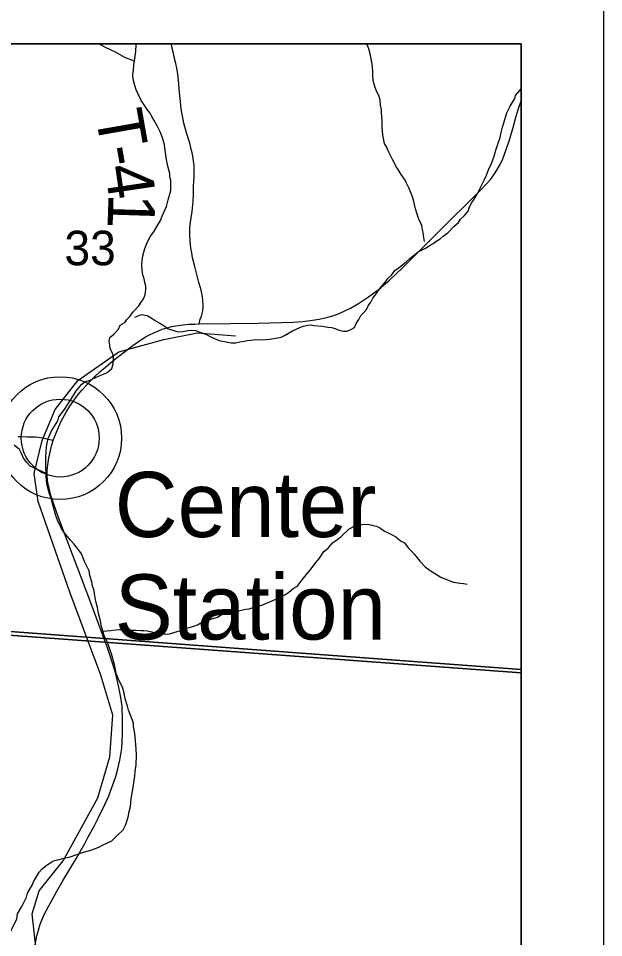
# Model space of a CAD drawing. Extents: x 0 to 82.7, y -0.2 to 22.
# Drawn here: x 8.291 to 9, y 19.817 to 20.931 of the extents above; entities that cross this region are included whole.
import ezdxf

# ---------------------------------------------------------------- set-up
doc = ezdxf.new("R2010")
doc.units = 0
for name, color, linetype in [('GM_X_County_Road', 7, 'Continuous'), ('GM_X_Minor_River', 7, 'Continuous'), ('GM_X_Rail_Line', 7, 'Continuous'), ('GM_X_Section_Text', 7, 'Continuous'), ('GM_X_State_Route', 7, 'Continuous'), ('GM_X_Township_Road', 7, 'Continuous'), ('GM_X_Township_Road_Text', 7, 'Continuous'), ('GM_X_Township_Text', 7, 'Continuous'), ('GM_X_Unincorporated', 7, 'Continuous'), ('GM_X_Unincorporated_Location', 7, 'Continuous'), ('GM_X_Unincorporated_Text', 7, 'Continuous'), ('SH_Cut_Line', 7, 'Continuous'), ('SH_Data', 7, 'Continuous')]:
    doc.layers.add(name, color=color, linetype=linetype)

msp = doc.modelspace()

# ---------------------------------------------------------------- linework, layer by layer
at = {"layer": 'GM_X_County_Road'}
for points in [[(8.9, 20.1421), (8.9, 20.9), (8.0024, 20.9), (7.9492, 20.2127)], [(8.9, 19.3224), (8.9, 20.1421), (7.9492, 20.2127), (7.8698, 19.2002), (8.8838, 19.1258)]]:
    msp.add_lwpolyline(points, close=True, dxfattribs=at)
msp.add_lwpolyline([(8.2907, 20.4244), (8.2947, 20.4244), (8.3015, 20.4241), (8.3116, 20.4239), (8.3204, 20.4229), (8.3271, 20.4212), (8.333, 20.4197)], dxfattribs=at)
at = {"layer": 'GM_X_Minor_River'}
for points in [[(8.4314, 20.8791), (8.4207, 20.883), (8.4086, 20.89), (8.3966, 20.8957), (8.3885, 20.9)], [(8.402, 20.5306), (8.4017, 20.5348), (8.401, 20.5398), (8.4018, 20.5443), (8.4064, 20.5484), (8.4122, 20.5545), (8.4141, 20.5594), (8.4198, 20.5623), (8.4225, 20.5661), (8.426, 20.5699), (8.4302, 20.5759), (8.4368, 20.5826), (8.4398, 20.5872), (8.4425, 20.5913), (8.4445, 20.5959), (8.4453, 20.6027), (8.4454, 20.6065), (8.4443, 20.6111), (8.4432, 20.6153), (8.4417, 20.6202), (8.441, 20.6259), (8.4404, 20.632), (8.4408, 20.6377), (8.4416, 20.6434), (8.444, 20.6521), (8.4475, 20.66), (8.451, 20.6672), (8.4549, 20.6725), (8.4595, 20.68), (8.463, 20.6861), (8.4653, 20.6914), (8.4681, 20.6978), (8.4704, 20.7031), (8.4724, 20.711), (8.474, 20.7167), (8.4755, 20.7224), (8.4757, 20.7349), (8.4746, 20.7391), (8.4743, 20.7429), (8.4721, 20.7517), (8.4699, 20.762), (8.4696, 20.7658), (8.4689, 20.7708), (8.4678, 20.7776), (8.466, 20.7849), (8.4631, 20.7925), (8.459, 20.8009), (8.4553, 20.8074), (8.4527, 20.812), (8.4505, 20.8162), (8.4471, 20.8204), (8.4441, 20.825), (8.4396, 20.8316), (8.4359, 20.8392), (8.4337, 20.8442), (8.4319, 20.8495), (8.4301, 20.8572), (8.4294, 20.8625), (8.4302, 20.8682), (8.4306, 20.8746), (8.4319, 20.8822), (8.4331, 20.8909), (8.4336, 20.8993), (8.4336, 20.9)], [(8.7829, 20.6607), (8.7818, 20.668), (8.7815, 20.6721), (8.78, 20.6767), (8.7797, 20.6805), (8.7767, 20.6866), (8.7742, 20.6939), (8.772, 20.7), (8.7709, 20.7053), (8.7702, 20.7092), (8.7683, 20.7149), (8.7661, 20.7206), (8.7639, 20.7256), (8.7613, 20.7313), (8.7595, 20.7351), (8.7546, 20.7417), (8.7509, 20.7478), (8.7483, 20.752), (8.7464, 20.7562), (8.7442, 20.76), (8.7416, 20.765), (8.7394, 20.7696), (8.7368, 20.7753), (8.7346, 20.7795), (8.7324, 20.7895), (8.7318, 20.7997), (8.7315, 20.8073), (8.7308, 20.8165), (8.7309, 20.8203), (8.7298, 20.8256), (8.7291, 20.8317), (8.7276, 20.8374), (8.725, 20.8428), (8.7232, 20.847), (8.7214, 20.8523), (8.7207, 20.8565), (8.7203, 20.8611), (8.7204, 20.8668), (8.7201, 20.8713), (8.7197, 20.8755), (8.7179, 20.8839), (8.7172, 20.8881), (8.7154, 20.8942), (8.7132, 20.9)], [(8.8931, 20.8376), (8.8984, 20.8436), (8.9, 20.8455)], [(8.432, 20.569), (8.4401, 20.5723), (8.4469, 20.5711), (8.4529, 20.5672), (8.4578, 20.5641), (8.4623, 20.5618), (8.4676, 20.5583), (8.4717, 20.5552), (8.4804, 20.5525), (8.4842, 20.5513), (8.4903, 20.5516), (8.4964, 20.5526), (8.5001, 20.553), (8.5055, 20.5529), (8.5108, 20.5509), (8.5179, 20.5482), (8.524, 20.5451), (8.5285, 20.5431), (8.5342, 20.5407), (8.5406, 20.5395), (8.5489, 20.5379), (8.5542, 20.5378), (8.5592, 20.5389), (8.5645, 20.54), (8.5687, 20.5407), (8.5725, 20.541), (8.5778, 20.5417), (8.5858, 20.5416), (8.5953, 20.5422), (8.6029, 20.5433), (8.6093, 20.5447), (8.6135, 20.5466), (8.6231, 20.5522), (8.6276, 20.5544), (8.6318, 20.5566), (8.6364, 20.5581), (8.6417, 20.5591), (8.6455, 20.5595), (8.6493, 20.559), (8.6592, 20.5582), (8.666, 20.5569), (8.6702, 20.5565), (8.6747, 20.5553), (8.6792, 20.553), (8.6849, 20.5521), (8.6891, 20.5521), (8.6944, 20.5543), (8.6982, 20.5565), (8.7002, 20.5611), (8.7036, 20.566), (8.706, 20.5709), (8.7094, 20.5746), (8.7125, 20.5784), (8.7148, 20.5825), (8.7179, 20.5871), (8.7203, 20.592), (8.723, 20.5957), (8.728, 20.6025), (8.7314, 20.6066), (8.7353, 20.6115), (8.7391, 20.6161), (8.743, 20.6198), (8.7472, 20.6255), (8.7522, 20.6292), (8.7568, 20.6326), (8.7606, 20.6359), (8.7652, 20.64), (8.7694, 20.6434), (8.7755, 20.6479), (8.7843, 20.6527), (8.7897, 20.6561), (8.7935, 20.6583), (8.7973, 20.6609), (8.8019, 20.6639), (8.8057, 20.6669), (8.8111, 20.671), (8.8191, 20.6793), (8.8241, 20.6838), (8.8265, 20.6875), (8.8311, 20.6917), (8.8357, 20.6973), (8.8376, 20.7026), (8.8403, 20.7079), (8.843, 20.7117), (8.8469, 20.7181), (8.8524, 20.7294), (8.8555, 20.7358), (8.8582, 20.7411), (8.8605, 20.7475), (8.864, 20.7551), (8.8672, 20.7638), (8.8695, 20.7714), (8.8723, 20.7797), (8.8746, 20.7865), (8.8758, 20.7926), (8.8774, 20.799), (8.8794, 20.8058), (8.8829, 20.8164), (8.8868, 20.8247), (8.8923, 20.8338), (8.8931, 20.8376)], [(8.3196, 19.9005), (8.3242, 19.9042), (8.3307, 19.9087), (8.3345, 19.9105), (8.3403, 19.912), (8.3448, 19.9131), (8.3536, 19.9152), (8.3619, 19.9178), (8.3699, 19.9207), (8.3787, 19.9233), (8.3882, 19.9269), (8.3928, 19.9292), (8.4042, 19.9343), (8.41, 19.9403), (8.4177, 19.9478), (8.4212, 19.9543), (8.4239, 19.963), (8.4251, 19.9698), (8.4267, 19.9759), (8.4272, 19.9804), (8.4276, 19.9857), (8.4292, 19.9941), (8.4321, 20.0126), (8.4325, 20.0183), (8.4338, 20.0267), (8.4339, 20.0388), (8.4336, 20.0453), (8.433, 20.0556), (8.4319, 20.0643), (8.4305, 20.0731), (8.4302, 20.0769), (8.4276, 20.0845), (8.4243, 20.0929), (8.4232, 20.0975), (8.4203, 20.1063), (8.4192, 20.1135), (8.417, 20.1208), (8.4129, 20.1284), (8.4092, 20.1372), (8.4075, 20.1479), (8.4038, 20.1608), (8.4001, 20.1711), (8.3976, 20.1776), (8.3953, 20.1822), (8.3931, 20.1883), (8.3917, 20.1941), (8.3902, 20.2009), (8.3881, 20.2097), (8.3866, 20.2173), (8.3848, 20.2245), (8.383, 20.2341), (8.3827, 20.2379), (8.3809, 20.2428), (8.3798, 20.2482), (8.3776, 20.2558), (8.3765, 20.2615), (8.371, 20.273), (8.3673, 20.2822), (8.3628, 20.2883), (8.3579, 20.2941), (8.3542, 20.2987), (8.3505, 20.3033), (8.346, 20.3086), (8.3422, 20.3144), (8.3382, 20.3228), (8.336, 20.3297), (8.3341, 20.3358), (8.3323, 20.3426), (8.3309, 20.3484), (8.3287, 20.3548), (8.3268, 20.3606), (8.3254, 20.3674), (8.3247, 20.375), (8.3244, 20.3796), (8.3241, 20.3868), (8.3242, 20.3963), (8.3243, 20.4001), (8.3247, 20.4062), (8.3248, 20.4119), (8.3256, 20.4161), (8.3268, 20.4221), (8.3307, 20.4305), (8.3388, 20.4433), (8.34, 20.4482), (8.3469, 20.4569), (8.3539, 20.4682), (8.3581, 20.475), (8.3608, 20.4795), (8.3678, 20.4877), (8.3716, 20.4907), (8.3777, 20.4926), (8.3842, 20.4959), (8.388, 20.4974), (8.3941, 20.5), (8.3983, 20.5018), (8.404, 20.5067), (8.4056, 20.5124), (8.406, 20.5165), (8.4061, 20.5211), (8.405, 20.5253), (8.402, 20.5306)], [(8.3244, 20.3796), (8.3051, 20.3882), (8.301, 20.3928), (8.2973, 20.3982), (8.2947, 20.4039), (8.2921, 20.4085), (8.2857, 20.4139)], [(8.3931, 20.1883), (8.403, 20.1893), (8.4091, 20.19), (8.4136, 20.1904), (8.4178, 20.1903), (8.4235, 20.1898), (8.433, 20.1897), (8.4391, 20.1893), (8.4428, 20.1892), (8.447, 20.1888), (8.4527, 20.1876), (8.4568, 20.1864), (8.4618, 20.1852), (8.4693, 20.1847), (8.4743, 20.1854), (8.4792, 20.1869), (8.4834, 20.1879), (8.4891, 20.1898), (8.4964, 20.1927), (8.5036, 20.1945), (8.5078, 20.196), (8.517, 20.2012), (8.5257, 20.2034), (8.5322, 20.2056), (8.5375, 20.2085), (8.5413, 20.2092), (8.547, 20.2107), (8.5539, 20.2129), (8.5592, 20.2136), (8.5664, 20.215), (8.5706, 20.2157), (8.5775, 20.2179), (8.5813, 20.2186), (8.5858, 20.2201), (8.6019, 20.2267), (8.6137, 20.2323), (8.6187, 20.2356), (8.624, 20.2401), (8.629, 20.2431), (8.6321, 20.2472), (8.6378, 20.2548), (8.6455, 20.2638), (8.6502, 20.2702), (8.6556, 20.277), (8.661, 20.2849), (8.6663, 20.289), (8.6717, 20.2954), (8.6778, 20.2999), (8.682, 20.3032), (8.6916, 20.3126), (8.7, 20.3167), (8.7072, 20.3177), (8.7141, 20.318), (8.7194, 20.3168), (8.7243, 20.3156), (8.7284, 20.314), (8.7345, 20.3098), (8.7382, 20.3082), (8.7439, 20.3051), (8.7484, 20.3028), (8.7537, 20.2981), (8.7586, 20.2954), (8.7631, 20.2893), (8.7676, 20.285), (8.7709, 20.2812), (8.7773, 20.2731), (8.7837, 20.2666), (8.7897, 20.262), (8.8029, 20.2538), (8.8097, 20.2511), (8.8183, 20.2479), (8.8263, 20.2467), (8.8301, 20.2462), (8.8346, 20.2454)], [(8.2795, 19.8109), (8.28, 19.8177), (8.28, 19.8219), (8.2835, 19.8283), (8.289, 19.84), (8.2898, 19.8461), (8.2952, 19.8548), (8.3006, 19.8661), (8.3018, 19.871), (8.3076, 19.8805), (8.3092, 19.8846), (8.3138, 19.8925), (8.3162, 19.8963), (8.3196, 19.9005)]]:
    msp.add_lwpolyline(points, dxfattribs=at)
at = {"layer": 'GM_X_Rail_Line'}
msp.add_lwpolyline([(8.5384, 19.2118), (8.5452, 19.2507), (8.5252, 19.3312), (8.3539, 19.5687), (8.333, 19.6161), (8.3075, 19.8461), (8.3159, 19.8739), (8.345, 19.9102), (8.3873, 19.9864), (8.4018, 20.036), (8.4054, 20.0868), (8.3909, 20.1352), (8.3534, 20.2356), (8.3147, 20.3457), (8.3099, 20.3796), (8.3196, 20.4195), (8.3353, 20.457), (8.3631, 20.4921), (8.4126, 20.5271), (8.467, 20.5417), (8.5081, 20.5501), (8.5541, 20.5465)], dxfattribs=at)
at = {"layer": 'GM_X_State_Route'}
for points in [[(8.3965, 20.1746), (8.3942, 20.1812), (8.3801, 20.2195), (8.3662, 20.2561), (8.35, 20.2983), (8.3395, 20.3263), (8.3304, 20.3528), (8.328, 20.3617), (8.3267, 20.3679), (8.326, 20.3719), (8.3258, 20.3769), (8.3258, 20.3815), (8.3261, 20.3873), (8.3278, 20.3984), (8.3311, 20.4126), (8.333, 20.4197), (8.337, 20.4297), (8.3428, 20.4429), (8.3487, 20.4538), (8.3533, 20.4611), (8.3572, 20.4669), (8.3618, 20.473), (8.3677, 20.4805), (8.3745, 20.4877), (8.3779, 20.4914), (8.3832, 20.4965), (8.3897, 20.5026), (8.3919, 20.5047), (8.3963, 20.5085), (8.4024, 20.5137), (8.4072, 20.5175), (8.4142, 20.523), (8.4178, 20.5258), (8.4279, 20.5334), (8.4342, 20.538), (8.4408, 20.5423), (8.4451, 20.545), (8.4499, 20.5475), (8.4552, 20.5501), (8.4598, 20.5521), (8.4653, 20.5543), (8.471, 20.556), (8.4763, 20.5575), (8.4813, 20.5585), (8.4875, 20.5594), (8.497, 20.5603), (8.5049, 20.5605), (8.5101, 20.561), (8.548, 20.5613), (8.5813, 20.5618), (8.624, 20.563), (8.6357, 20.5638), (8.6471, 20.5651), (8.6553, 20.5664), (8.6644, 20.5685), (8.6719, 20.5707), (8.6796, 20.5734), (8.6802, 20.5738), (8.6934, 20.58), (8.703, 20.5855), (8.7153, 20.5937), (8.7213, 20.5981), (8.7299, 20.6046), (8.7303, 20.6051), (8.7407, 20.6139), (8.7566, 20.629), (8.7751, 20.6477), (8.7945, 20.667), (8.81, 20.6825), (8.8184, 20.6908), (8.8299, 20.7019), (8.8378, 20.7097), (8.8513, 20.7231), (8.8633, 20.7363), (8.8679, 20.7427), (8.8706, 20.7469), (8.875, 20.7547), (8.878, 20.7608), (8.8817, 20.771), (8.8854, 20.7827), (8.8883, 20.792), (8.8907, 20.8003), (8.8934, 20.8095), (8.8956, 20.8176), (8.8981, 20.8255), (8.9, 20.8308)], [(8.3112, 19.8083), (8.3132, 19.8193), (8.3151, 19.8263), (8.3172, 19.8334), (8.32, 19.8403), (8.3225, 19.8459), (8.3369, 19.8727), (8.3451, 19.8869), (8.3612, 19.9134), (8.3713, 19.9311), (8.3752, 19.9385), (8.3826, 19.9523), (8.3879, 19.9625), (8.3957, 19.9783), (8.4003, 19.9888), (8.4043, 19.9989), (8.4071, 20.0067), (8.4089, 20.0122), (8.4115, 20.0216), (8.4137, 20.032), (8.4161, 20.0468), (8.4172, 20.0636), (8.4172, 20.0807), (8.4166, 20.0974), (8.4152, 20.1082), (8.4123, 20.1224), (8.4089, 20.1366), (8.405, 20.1496), (8.4016, 20.1598), (8.3988, 20.1684), (8.3965, 20.1746)]]:
    msp.add_lwpolyline(points, dxfattribs=at)
at = {"layer": 'GM_X_Township_Road'}
msp.add_lwpolyline([(8.5101, 20.561), (8.5113, 20.5664), (8.5126, 20.5701), (8.5143, 20.5766), (8.5147, 20.5806), (8.5149, 20.5841), (8.5145, 20.5892), (8.5138, 20.5939), (8.5118, 20.6032), (8.5096, 20.6109), (8.5045, 20.6305), (8.5019, 20.641), (8.5009, 20.6467), (8.5, 20.6525), (8.499, 20.6613), (8.4986, 20.6683), (8.4985, 20.6752), (8.499, 20.6817), (8.5014, 20.6971), (8.5026, 20.7089), (8.5031, 20.7179), (8.5032, 20.7274), (8.5039, 20.7391), (8.504, 20.7471), (8.5037, 20.7532), (8.5032, 20.7579), (8.5023, 20.764), (8.5015, 20.768), (8.5007, 20.771), (8.4985, 20.7796), (8.4948, 20.7923), (8.4914, 20.804), (8.4904, 20.8083), (8.4892, 20.8149), (8.4883, 20.8213), (8.4873, 20.8301), (8.4863, 20.8413), (8.4858, 20.846), (8.4852, 20.8518), (8.4844, 20.8601), (8.4838, 20.8662), (8.483, 20.8708), (8.4817, 20.8761), (8.4798, 20.8839), (8.4791, 20.8869), (8.4781, 20.8919), (8.477, 20.8965), (8.4765, 20.9)], dxfattribs=at)
at = {"layer": 'GM_X_Township_Text'}
msp.add_lwpolyline([(8.9, 20.1381), (8.9, 20.9), (6.1272, 20.9), (5.9756, 20.3782), (5.9672, 20.3493), (5.9906, 20.3478), (6.0773, 20.3422), (6.1569, 20.3371), (6.2809, 20.329), (6.7144, 20.301), (6.9227, 20.2875), (7.9434, 20.2083), (8.3897, 20.1756)], close=True, dxfattribs=at)
msp.add_lwpolyline([(8.9, 14.1), (8.9, 20.1381), (8.3897, 20.1756), (7.9434, 20.2083), (6.9227, 20.2875), (6.7144, 20.301), (6.2809, 20.329), (6.1569, 20.3371), (6.0773, 20.3422), (5.9906, 20.3478), (5.9672, 20.3493), (3.6288, 20.5056)], dxfattribs=at)
at = {"layer": 'GM_X_Unincorporated'}
for radius in [0.0744, 0.0472]:
    msp.add_circle((8.3416, 20.4224), radius, dxfattribs=at)
at = {"layer": 'GM_X_Unincorporated_Location'}
msp.add_line((8.3416, 20.4224), (8.3416, 20.4224), dxfattribs=at)
at = {"layer": 'SH_Cut_Line'}
msp.add_lwpolyline([(8.9, 14.1), (8.9, 20.9), (6.1272, 20.9), (5.9756, 20.3782), (5.9672, 20.3493), (3.6288, 20.5056), (3.179, 20.5374), (2.884, 20.5583), (2.8651, 20.279), (2.8645, 20.2703), (2.8645, 20.2693), (2.8288, 19.7415), (2.7788, 19.0007), (2.7784, 18.9951), (2.7199, 18.1299), (3.0279, 17.3486), (3.0556, 17.2782), (3.2909, 16.7562), (3.4071, 16.476), (3.6125, 15.9807), (3.8036, 15.5496), (4.1209, 14.8338)], dxfattribs=at)
at = {"layer": 'SH_Data'}
for p, q in [((9, 21), (9, 14)), ((2.1, 20.9), (8.9, 20.9)), ((8.9, 20.9), (8.9, 14.1))]:
    msp.add_line(p, q, dxfattribs=at)

# ---------------------------------------------------------------- texts
at = {"layer": 'GM_X_Section_Text'}
msp.add_text('33', height=0.04186, rotation=0, dxfattribs=at).set_placement((8.3467, 20.6318))
at = {"layer": 'GM_X_Township_Road_Text'}
for s, rotation, p in [('T', 279.9583, (8.3839, 20.8155)), ('-', 279.805, (8.3913, 20.7737)), ('4', 278.4558, (8.3952, 20.7511)), ('1', 268.2095, (8.4002, 20.7191))]:
    msp.add_text(s, height=0.0568, rotation=rotation, dxfattribs=at).set_placement(p)
at = {"layer": 'GM_X_Unincorporated_Text'}
for s, p in [('Center', (8.4076, 20.3025)), ('Station', (8.4076, 20.1783))]:
    msp.add_text(s, height=0.07898, rotation=0, dxfattribs=at).set_placement(p)

doc.saveas('drawing.dxf')
